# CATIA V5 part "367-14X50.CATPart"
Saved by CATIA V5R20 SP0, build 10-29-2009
Part number: 367-14X50
Definition: NONE
Nomenclature: 367-14X50
Source: Unknown
Description: 367-14X50
Bounding box of the stored display mesh (mm): x 0 to 50, y -14 to 14, z -14 to 14
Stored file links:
  C:\Users\Utente\Desktop\IO LAVORO\3D X SITO CF\X SITO\PLASTICA\3D files 367\367-14X50.CATPart
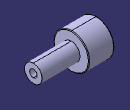
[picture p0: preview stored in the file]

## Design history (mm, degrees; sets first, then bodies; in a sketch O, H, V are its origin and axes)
Body1 "367-14X50" (main body)
  Solid1: solid without history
